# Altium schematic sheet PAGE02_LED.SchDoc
size 381 x 304 mm; SheetNumber: 3; SheetTotal: 28
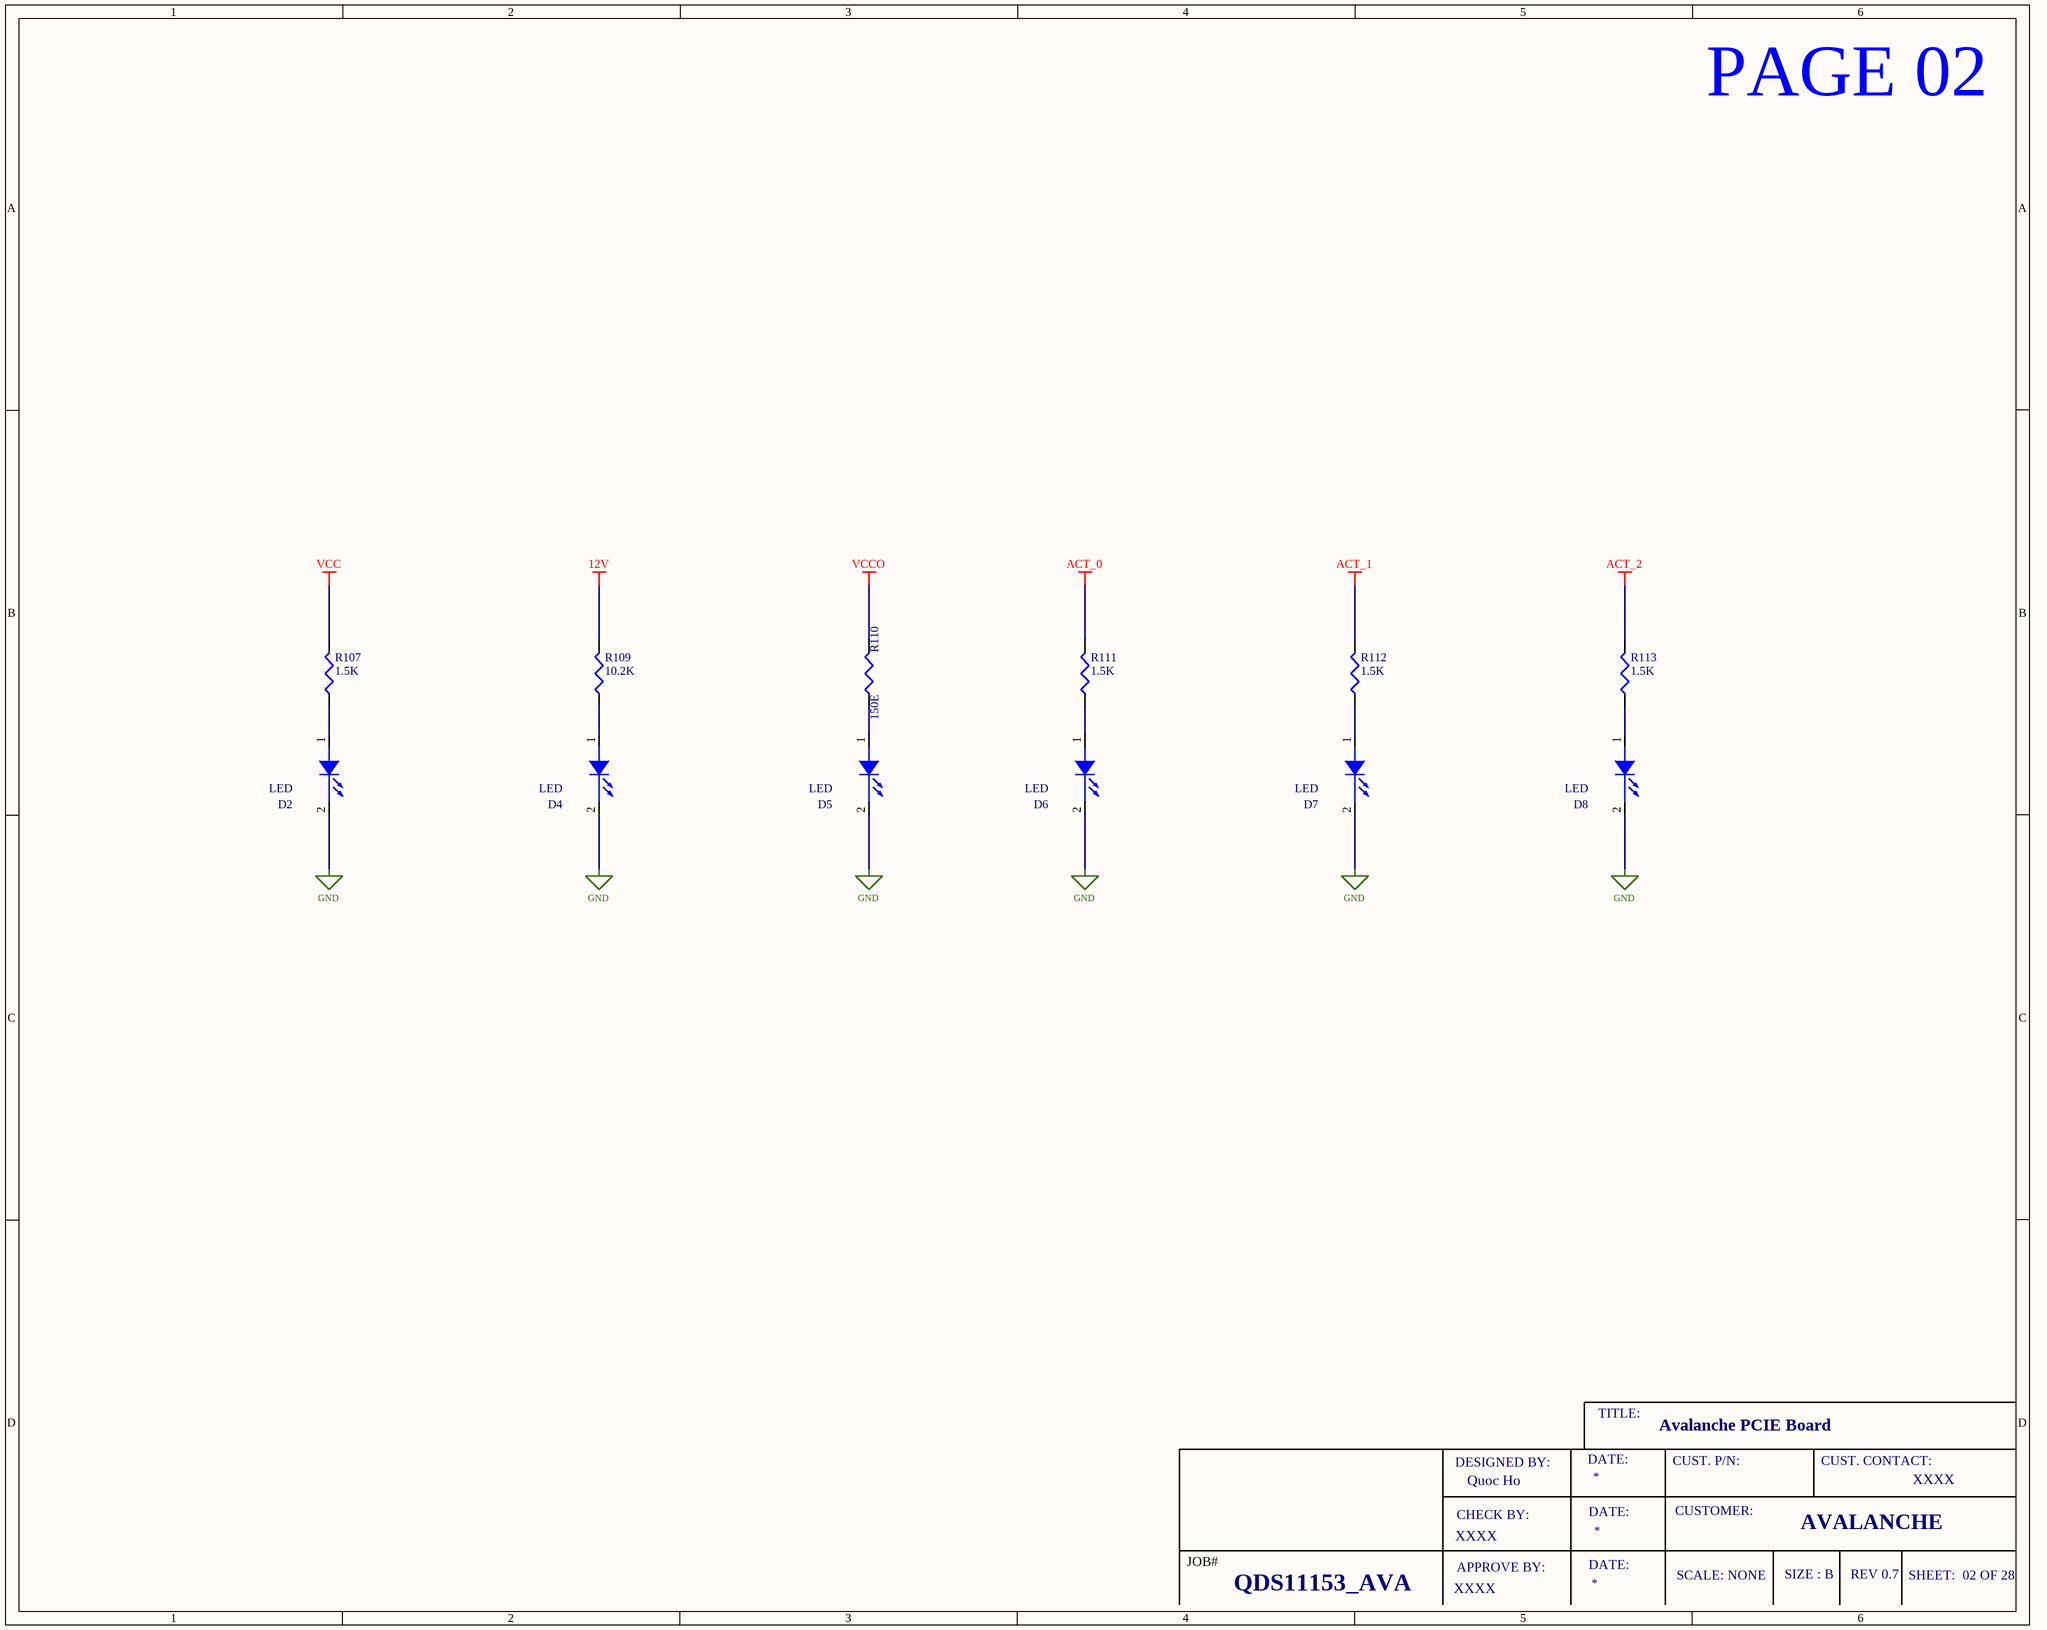
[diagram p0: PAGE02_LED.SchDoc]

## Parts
D2  LED  [LED_0603]
D4  LED  [LED_0603]
D5  LED  [LED_0603]
D6  LED  [LED_0603]
D7  LED  [LED_0603]
D8  LED  [LED_0603]
R107  1.5K  [RN_0402]
R109  10.2K  [RN_0402]
R110  150E  [RN_0402]
R111  1.5K  [RN_0402]
R112  1.5K  [RN_0402]
R113  1.5K  [RN_0402]

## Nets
12V: R109.2
ACT_0: R111.2
ACT_1: R112.2
ACT_2: R113.2
GND: D2.2 D4.2 D5.2 D6.2 D7.2 D8.2
VCC: R107.2
VCCO: R110.2
NetD2_1: D2.1 R107.1
NetD4_1: D4.1 R109.1
NetD5_1: D5.1 R110.1
NetD6_1: D6.1 R111.1
NetD7_1: D7.1 R112.1
NetD8_1: D8.1 R113.1

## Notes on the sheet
- PAGE 02
- TITLE:
- Avalanche PCIE Board
- DESIGNED BY:
- CHECK BY:
- Quoc Ho
- DATE:
- CUST. P/N:
- CUSTOMER:
- CUST. CONTACT:
- XXXX
- JOB#
- APPROVE BY:
- SCALE: NONE
- SIZE : B
- AVALANCHE
- REV 0.7
- SHEET:  02 OF 28
- QDS11153_AVA

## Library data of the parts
D2 D4-D8 = LED: LED GREEN CLEAR SMD; Manufacturer Part Number: LTST-C191KGKT; Manufacturer: Lite-On Inc.
R107 R111-R113 = RES: RES 1.5K OHM 1% 1/16W 0402; Manufacturer Part Number: RC0402FR-131K5L; Manufacturer: YAGEO
R109 = RES: RES 10.2K OHM 1% 1/16W 0402; Manufacturer Part Number: RC0402FR-0710K2L; Manufacturer: YAGEO
R110 = RES: RES 150 OHM 1% 1/16W 0402; Manufacturer Part Number: RC0402FR-07150RL; Manufacturer: YAGEO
